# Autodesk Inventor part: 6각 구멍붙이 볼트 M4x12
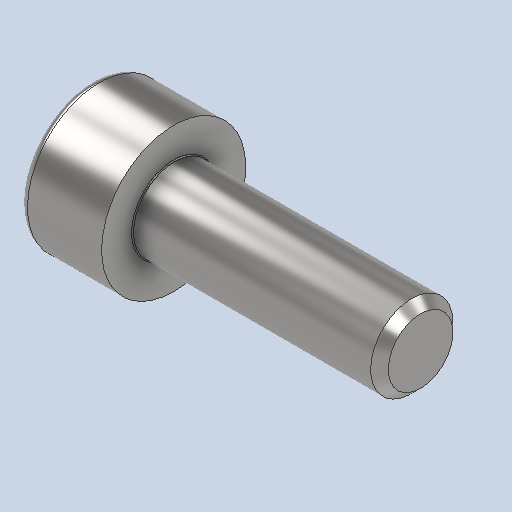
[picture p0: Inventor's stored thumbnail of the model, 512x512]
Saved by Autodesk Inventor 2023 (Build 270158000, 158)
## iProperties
Created: 2026-04
Part Number: 6각 구멍붙이 볼트 M4x12
Material: 강철, 연강
Description: 6각머리 태핑 나사
Document SubType Name: Modeling
Designer: 4강의실
Density: 7.85 g/cm^3
Appearance: 기본값
Author: jhkim
Sending System: Autodesk Inventor 2027
Preprocessor: ST-DEVELOPER v20.1
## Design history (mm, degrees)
feature "Solid1"
node "솔리드1"
